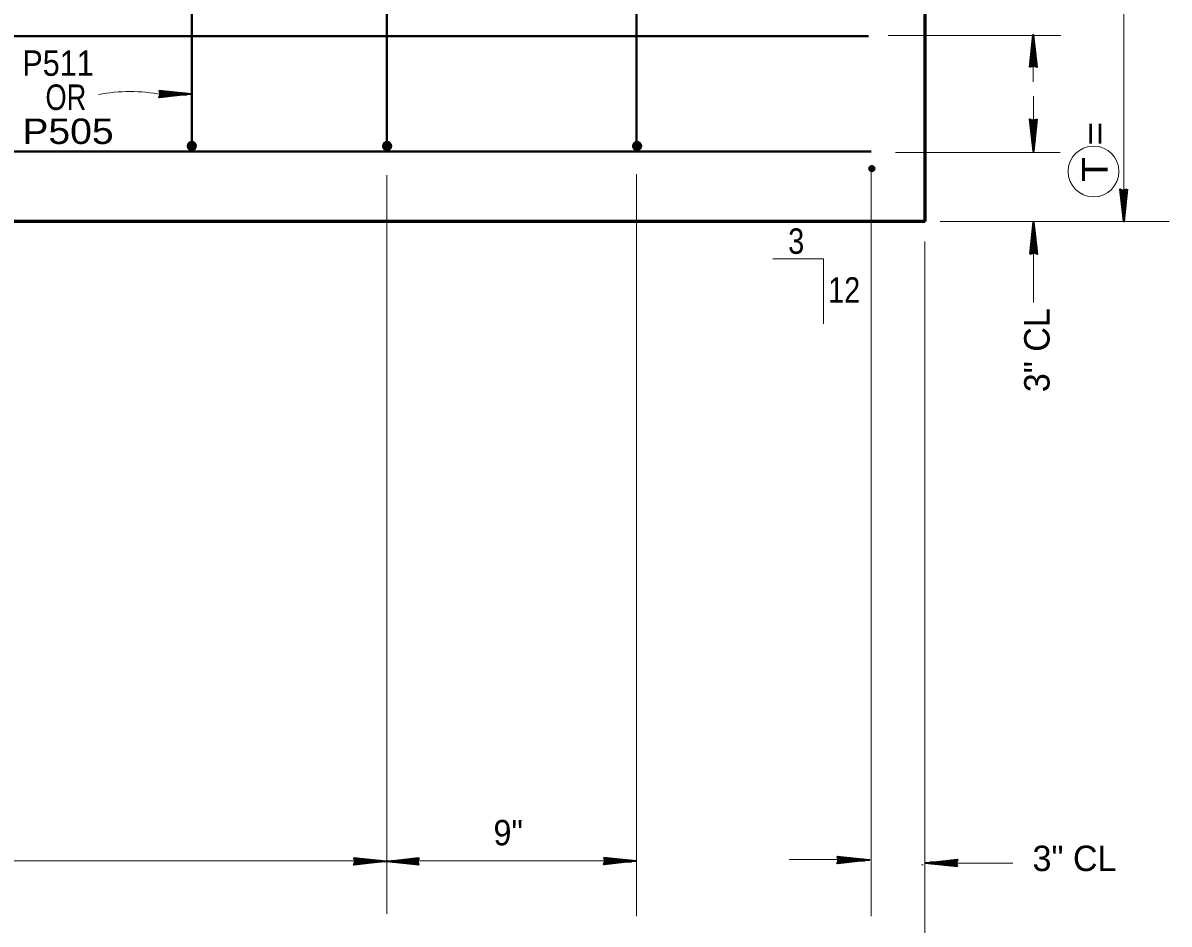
# Model space of a CAD drawing. Extents: x 6.34 to 9.53, y -1.46 to 0.53.
# Drawn here: x 7.0899 to 7.4656, y -1.0365 to -0.7412 of the extents above; entities that cross this region are included whole.
import ezdxf
from ezdxf.enums import TextEntityAlignment as Align

# ---------------------------------------------------------------- set-up
doc = ezdxf.new("R2010")
doc.units = 0
doc.header["$LTSCALE"] = 0.0033
doc.header["$PDMODE"] = 32
doc.header["$PDSIZE"] = 0.00165
doc.layers.add('1', color=7, linetype='Continuous', lineweight=40)

msp = doc.modelspace()

# ---------------------------------------------------------------- linework, layer by layer
at = {"layer": '1', "lineweight": 13}
for p, q in [((7.45075, -0.391417), (7.45075, -0.80625)), ((7.3735, -0.74525), (7.430083, -0.74525)), ((7.421083, -0.7605), (7.421083, -0.750583)), ((7.421167, -0.775), (7.421167, -0.765167)), ((7.209167, -0.774333), (7.209167, -0.782)), ((7.375917, -0.783583), (7.429917, -0.783583)), ((7.367917, -0.78775), (7.367917, -1.033917)), ((7.209167, -0.791083), (7.209167, -1.033083)), ((7.291083, -0.79075), (7.291083, -1.033917)), ((7.367917, -0.795917), (7.367917, -0.7975)), ((7.385583, -0.80625), (7.385583, -0.806583)), ((7.390583, -0.80625), (7.465583, -0.80625)), ((7.385583, -0.81275), (7.385583, -0.8945)), ((7.335667, -0.818417), (7.352333, -0.818417)), ((7.352333, -0.818417), (7.352333, -0.83975)), ((7.421167, -0.83275), (7.421167, -0.81625)), ((7.385583, -0.892917), (7.385583, -1.077833)), ((7.290917, -1.01575), (6.739167, -1.01575)), ((7.341083, -1.01525), (7.361917, -1.01525)), ((7.384417, -1.017), (7.385, -1.017)), ((7.393583, -1.0165), (7.414417, -1.0165)), ((7.291083, -1.0215), (7.291083, -1.02725)), ((7.209167, -1.024167), (7.209167, -1.029417))]:
    msp.add_line(p, q, dxfattribs=at)
at = {"layer": '1'}
for p, q in [((7.14525, -0.667917), (7.14525, -0.780417)), ((7.209167, -0.667917), (7.209167, -0.780333)), ((7.291083, -0.667667), (7.291083, -0.78)), ((7.144667, -0.780333), (7.144333, -0.782333)), ((7.14475, -0.780417), (7.144417, -0.782333)), ((7.144833, -0.780417), (7.1445, -0.782333)), ((7.144917, -0.780417), (7.144583, -0.782417)), ((7.146083, -0.780583), (7.144583, -0.7805)), ((7.146083, -0.780667), (7.144583, -0.780583)), ((7.146083, -0.78075), (7.144583, -0.780667)), ((7.146083, -0.780833), (7.144583, -0.78075)), ((7.146083, -0.780917), (7.144583, -0.780833)), ((7.146083, -0.781083), (7.144583, -0.781)), ((7.146083, -0.781167), (7.144583, -0.781083)), ((7.146083, -0.78125), (7.144583, -0.781167)), ((7.146083, -0.781333), (7.144583, -0.78125)), ((7.145167, -0.780417), (7.14475, -0.782417)), ((7.145333, -0.7805), (7.144917, -0.782417)), ((7.145417, -0.7805), (7.145, -0.782417)), ((7.1455, -0.7805), (7.145083, -0.7825)), ((7.145583, -0.7805), (7.14525, -0.7825)), ((7.145667, -0.780583), (7.145333, -0.7825)), ((7.145833, -0.780583), (7.145417, -0.782583)), ((7.145917, -0.780583), (7.1455, -0.782583)), ((7.146, -0.780583), (7.145667, -0.782583)), ((7.146083, -0.780583), (7.14575, -0.782583)), ((7.14625, -0.780667), (7.145917, -0.782583)), ((7.208667, -0.780333), (7.208333, -0.782333)), ((7.20875, -0.780417), (7.208417, -0.782333)), ((7.208833, -0.780417), (7.2085, -0.782333)), ((7.208917, -0.780417), (7.208583, -0.782417)), ((7.210083, -0.780583), (7.208583, -0.7805)), ((7.210083, -0.780667), (7.208583, -0.780583)), ((7.210083, -0.78075), (7.208583, -0.780667)), ((7.210083, -0.780833), (7.208583, -0.78075)), ((7.210083, -0.780917), (7.208583, -0.780833)), ((7.210083, -0.781083), (7.208583, -0.781)), ((7.210083, -0.781167), (7.208583, -0.781083)), ((7.210083, -0.78125), (7.208583, -0.781167)), ((7.210083, -0.781333), (7.208583, -0.78125)), ((7.209167, -0.780417), (7.20875, -0.782417)), ((7.209333, -0.7805), (7.208917, -0.782417)), ((7.209417, -0.7805), (7.209, -0.782417)), ((7.2095, -0.7805), (7.209083, -0.7825)), ((7.209583, -0.7805), (7.20925, -0.7825)), ((7.209667, -0.780583), (7.209333, -0.7825)), ((7.209833, -0.780583), (7.209417, -0.782583)), ((7.209917, -0.780583), (7.2095, -0.782583)), ((7.21, -0.780583), (7.209667, -0.782583)), ((7.210083, -0.780583), (7.20975, -0.782583)), ((7.21025, -0.780667), (7.209917, -0.782583)), ((7.290583, -0.780333), (7.29025, -0.782333)), ((7.290667, -0.780417), (7.290333, -0.782333)), ((7.29075, -0.780417), (7.290417, -0.782333)), ((7.290833, -0.780417), (7.2905, -0.782417)), ((7.292, -0.780583), (7.2905, -0.7805)), ((7.292, -0.780667), (7.2905, -0.780583)), ((7.292, -0.78075), (7.2905, -0.780667)), ((7.292, -0.780833), (7.2905, -0.78075)), ((7.292, -0.780917), (7.2905, -0.780833)), ((7.292, -0.781083), (7.2905, -0.781)), ((7.292, -0.781167), (7.2905, -0.781083)), ((7.292, -0.78125), (7.2905, -0.781167)), ((7.292, -0.781333), (7.2905, -0.78125)), ((7.291083, -0.780417), (7.290667, -0.782417)), ((7.29125, -0.7805), (7.290833, -0.782417)), ((7.291333, -0.7805), (7.290917, -0.782417)), ((7.291417, -0.7805), (7.291, -0.7825)), ((7.2915, -0.7805), (7.291167, -0.7825)), ((7.291583, -0.780583), (7.29125, -0.7825)), ((7.29175, -0.780583), (7.291333, -0.782583)), ((7.291833, -0.780583), (7.291417, -0.782583)), ((7.291917, -0.780583), (7.291583, -0.782583)), ((7.292, -0.780583), (7.291667, -0.782583)), ((7.292167, -0.780667), (7.291833, -0.782583)), ((7.146, -0.78175), (7.1445, -0.781583)), ((7.146, -0.781917), (7.1445, -0.78175)), ((7.146, -0.782), (7.1445, -0.781917)), ((7.146, -0.782), (7.1445, -0.781917)), ((7.146, -0.782083), (7.1445, -0.782)), ((7.146, -0.782167), (7.1445, -0.782083)), ((7.146, -0.78225), (7.1445, -0.782167)), ((7.146, -0.782333), (7.1445, -0.78225)), ((7.146, -0.782417), (7.1445, -0.782333)), ((7.146, -0.7825), (7.1445, -0.782417)), ((7.146, -0.782667), (7.1445, -0.782583)), ((7.146083, -0.781417), (7.144583, -0.781333)), ((7.146083, -0.7815), (7.144583, -0.781417)), ((7.146083, -0.781583), (7.144583, -0.7815)), ((7.21, -0.78175), (7.2085, -0.781583)), ((7.21, -0.781917), (7.2085, -0.78175)), ((7.21, -0.782), (7.2085, -0.781917)), ((7.21, -0.782), (7.2085, -0.781917)), ((7.21, -0.782083), (7.2085, -0.782)), ((7.21, -0.782167), (7.2085, -0.782083)), ((7.21, -0.78225), (7.2085, -0.782167)), ((7.21, -0.782333), (7.2085, -0.78225)), ((7.21, -0.782417), (7.2085, -0.782333)), ((7.21, -0.7825), (7.2085, -0.782417)), ((7.21, -0.782667), (7.2085, -0.782583)), ((7.210083, -0.781417), (7.208583, -0.781333)), ((7.210083, -0.7815), (7.208583, -0.781417)), ((7.210083, -0.781583), (7.208583, -0.7815)), ((7.291917, -0.78175), (7.290417, -0.781583)), ((7.291917, -0.781917), (7.290417, -0.78175)), ((7.291917, -0.782), (7.290417, -0.781917)), ((7.291917, -0.782), (7.290417, -0.781917)), ((7.291917, -0.782083), (7.290417, -0.782)), ((7.291917, -0.782167), (7.290417, -0.782083)), ((7.291917, -0.78225), (7.290417, -0.782167)), ((7.291917, -0.782333), (7.290417, -0.78225)), ((7.291917, -0.782417), (7.290417, -0.782333)), ((7.291917, -0.7825), (7.290417, -0.782417)), ((7.291917, -0.782667), (7.290417, -0.782583)), ((7.292, -0.781417), (7.2905, -0.781333)), ((7.292, -0.7815), (7.2905, -0.781417)), ((7.292, -0.781583), (7.2905, -0.7815))]:
    msp.add_line(p, q, dxfattribs=at)
at = {"layer": '1', "lineweight": 35}
for p, q in [((7.421083, -0.755667), (7.421083, -0.745083)), ((7.420083, -0.755417), (7.421, -0.747583)), ((7.420083, -0.755417), (7.421, -0.747583)), ((7.420167, -0.755417), (7.421, -0.747583)), ((7.42025, -0.755417), (7.421083, -0.747583)), ((7.42025, -0.755417), (7.42125, -0.747583)), ((7.42175, -0.7555), (7.421, -0.748167)), ((7.421917, -0.755417), (7.421083, -0.748083)), ((7.422, -0.755417), (7.42125, -0.748083)), ((7.422167, -0.755417), (7.421333, -0.748083)), ((7.134583, -0.764417), (7.145167, -0.764417)), ((7.13475, -0.765083), (7.142083, -0.764333)), ((7.134833, -0.763417), (7.142667, -0.764333)), ((7.134833, -0.763417), (7.142667, -0.764333)), ((7.134833, -0.7635), (7.142667, -0.764333)), ((7.134833, -0.763583), (7.142667, -0.764417)), ((7.134833, -0.763583), (7.142667, -0.764583)), ((7.134833, -0.76525), (7.142167, -0.764417)), ((7.134833, -0.765333), (7.142167, -0.764583)), ((7.134833, -0.7655), (7.142167, -0.764667)), ((7.420083, -0.772917), (7.420917, -0.78025)), ((7.42025, -0.772917), (7.421, -0.78025)), ((7.420333, -0.772917), (7.421167, -0.78025)), ((7.4205, -0.772833), (7.42125, -0.780167)), ((7.422, -0.772917), (7.421, -0.78075)), ((7.421167, -0.772667), (7.421167, -0.78325)), ((7.422, -0.772917), (7.421167, -0.78075)), ((7.422167, -0.772917), (7.42125, -0.78075)), ((7.422167, -0.772917), (7.42125, -0.78075)), ((7.422083, -0.772917), (7.42125, -0.78075)), ((7.449667, -0.795917), (7.4505, -0.80325)), ((7.449833, -0.795917), (7.450583, -0.80325)), ((7.449917, -0.795917), (7.45075, -0.80325)), ((7.450083, -0.795833), (7.450833, -0.803167)), ((7.451583, -0.795917), (7.450583, -0.80375)), ((7.45075, -0.795667), (7.45075, -0.80625)), ((7.451583, -0.795917), (7.45075, -0.80375)), ((7.45175, -0.795917), (7.450833, -0.80375)), ((7.45175, -0.795917), (7.450833, -0.80375)), ((7.451667, -0.795917), (7.450833, -0.80375)), ((7.421167, -0.816917), (7.421167, -0.806333)), ((7.420167, -0.816667), (7.421083, -0.808833)), ((7.420167, -0.816667), (7.421083, -0.808833)), ((7.42025, -0.816667), (7.421083, -0.808833)), ((7.420333, -0.816667), (7.421167, -0.808833)), ((7.420333, -0.816667), (7.421333, -0.808833)), ((7.421833, -0.81675), (7.421083, -0.809417)), ((7.422, -0.816667), (7.421167, -0.809333)), ((7.422083, -0.816667), (7.421333, -0.809333)), ((7.42225, -0.816667), (7.421417, -0.809333)), ((7.198417, -1.015833), (7.209, -1.015833)), ((7.198583, -1.0165), (7.205917, -1.01575)), ((7.198667, -1.014833), (7.2065, -1.01575)), ((7.198667, -1.014833), (7.2065, -1.01575)), ((7.198667, -1.014917), (7.2065, -1.01575)), ((7.198667, -1.015), (7.2065, -1.015833)), ((7.198667, -1.015), (7.2065, -1.016)), ((7.198667, -1.016667), (7.206, -1.015833)), ((7.198667, -1.01675), (7.206, -1.016)), ((7.198667, -1.016917), (7.206, -1.016083)), ((7.21975, -1.016), (7.209167, -1.016)), ((7.2195, -1.016833), (7.211667, -1.015833)), ((7.2195, -1.016833), (7.211667, -1.016)), ((7.2195, -1.017), (7.211667, -1.016083)), ((7.2195, -1.017), (7.211667, -1.016083)), ((7.2195, -1.016917), (7.211667, -1.016083)), ((7.2195, -1.014917), (7.212167, -1.01575)), ((7.2195, -1.015083), (7.212167, -1.015833)), ((7.2195, -1.015167), (7.212167, -1.016)), ((7.219583, -1.015333), (7.21225, -1.016083)), ((7.280333, -1.01575), (7.290917, -1.01575)), ((7.2805, -1.016417), (7.287833, -1.015667)), ((7.280583, -1.01475), (7.288417, -1.015667)), ((7.280583, -1.01475), (7.288417, -1.015667)), ((7.280583, -1.014833), (7.288417, -1.015667)), ((7.280583, -1.014917), (7.288417, -1.01575)), ((7.280583, -1.014917), (7.288417, -1.015917)), ((7.280583, -1.016583), (7.287917, -1.01575)), ((7.280583, -1.016667), (7.287917, -1.015917)), ((7.280583, -1.016833), (7.287917, -1.016)), ((7.356833, -1.015417), (7.367417, -1.015417)), ((7.357, -1.016083), (7.364333, -1.015333)), ((7.357083, -1.014417), (7.364917, -1.015333)), ((7.357083, -1.014417), (7.364917, -1.015333)), ((7.357083, -1.0145), (7.364917, -1.015333)), ((7.357083, -1.014583), (7.364917, -1.015417)), ((7.357083, -1.014583), (7.364917, -1.015583)), ((7.357083, -1.01625), (7.364417, -1.015417)), ((7.357083, -1.016333), (7.364417, -1.015583)), ((7.357083, -1.0165), (7.364417, -1.015667)), ((7.39625, -1.0165), (7.385667, -1.0165)), ((7.396, -1.017333), (7.388167, -1.016333)), ((7.396, -1.017333), (7.388167, -1.0165)), ((7.396, -1.0175), (7.388167, -1.016583)), ((7.396, -1.0175), (7.388167, -1.016583)), ((7.396, -1.017417), (7.388167, -1.016583)), ((7.396, -1.015417), (7.388667, -1.01625)), ((7.396, -1.015583), (7.388667, -1.016333)), ((7.396, -1.015667), (7.388667, -1.0165)), ((7.396083, -1.015833), (7.38875, -1.016583))]:
    msp.add_line(p, q, dxfattribs=at)
at = {"layer": '1', "lineweight": 60}
msp.add_line((7.385583, -0.80625), (6.635583, -0.80625), dxfattribs=at)
msp.add_lwpolyline([(7.30225, -0.389583), (7.30225, -0.722917), (7.385583, -0.722917), (7.385583, -0.80625)], dxfattribs=at)
at = {"layer": '1'}
for points in [[(6.962083, -0.741333), (7.024417, -0.741333), (7.031667, -0.7455), (7.367083, -0.7455)], [(6.962167, -0.779083), (7.02375, -0.779083), (7.031, -0.78325), (7.367917, -0.78325)], [(7.14525, -0.780167), (7.145583, -0.78275), (7.146083, -0.780417), (7.145, -0.78275), (7.144583, -0.780333), (7.14425, -0.782333), (7.146333, -0.782333), (7.144, -0.781417), (7.146583, -0.781667), (7.14425, -0.780667), (7.146583, -0.781), (7.144, -0.781833), (7.14575, -0.78025), (7.145917, -0.782667), (7.144083, -0.781), (7.1465, -0.782083), (7.146083, -0.780417), (7.144583, -0.780333), (7.144, -0.781417), (7.14425, -0.782333), (7.145, -0.78275), (7.145917, -0.782667), (7.1465, -0.782083), (7.145417, -0.781417), (7.1445, -0.782583), (7.14425, -0.780667), (7.145417, -0.781417), (7.145917, -0.780333), (7.146583, -0.781333), (7.1455, -0.781417), (7.14425, -0.78225), (7.1455, -0.78025), (7.145833, -0.781583), (7.146333, -0.782333)], [(7.20925, -0.780167), (7.209583, -0.78275), (7.210083, -0.780417), (7.209, -0.78275), (7.208583, -0.780333), (7.20825, -0.782333), (7.210333, -0.782333), (7.208, -0.781417), (7.210583, -0.781667), (7.20825, -0.780667), (7.210583, -0.781), (7.208, -0.781833), (7.20975, -0.78025), (7.209917, -0.782667), (7.208083, -0.781), (7.2105, -0.782083), (7.210083, -0.780417), (7.208583, -0.780333), (7.208, -0.781417), (7.20825, -0.782333), (7.209, -0.78275), (7.209917, -0.782667), (7.2105, -0.782083), (7.209417, -0.781417), (7.2085, -0.782583), (7.20825, -0.780667), (7.209417, -0.781417), (7.209917, -0.780333), (7.210583, -0.781333), (7.2095, -0.781417), (7.20825, -0.78225), (7.2095, -0.78025), (7.209833, -0.781583), (7.210333, -0.782333)], [(7.291167, -0.780167), (7.2915, -0.78275), (7.292, -0.780417), (7.290917, -0.78275), (7.2905, -0.780333), (7.290167, -0.782333), (7.29225, -0.782333), (7.289917, -0.781417), (7.2925, -0.781667), (7.290167, -0.780667), (7.2925, -0.781), (7.289917, -0.781833), (7.291667, -0.78025), (7.291833, -0.782667), (7.29, -0.781), (7.292417, -0.782083), (7.292, -0.780417), (7.2905, -0.780333), (7.289917, -0.781417), (7.290167, -0.782333), (7.290917, -0.78275), (7.291833, -0.782667), (7.292417, -0.782083), (7.291333, -0.781417), (7.290417, -0.782583), (7.290167, -0.780667), (7.291333, -0.781417), (7.291833, -0.780333), (7.2925, -0.781333), (7.291417, -0.781417), (7.290167, -0.78225), (7.291417, -0.78025), (7.29175, -0.781583), (7.29225, -0.782333)]]:
    msp.add_lwpolyline(points, dxfattribs=at)
at = {"layer": '1', "lineweight": 35}
for points in [[(7.42, -0.755667), (7.421083, -0.745083), (7.42225, -0.755667), (7.421083, -0.755083)], [(7.421, -0.754917), (7.420917, -0.75025), (7.421, -0.75025), (7.421, -0.751167), (7.420917, -0.754917), (7.420833, -0.751917), (7.42075, -0.755083), (7.420667, -0.752833), (7.420583, -0.755083), (7.420833, -0.751583), (7.421, -0.746917), (7.42125, -0.747833), (7.42125, -0.746583), (7.42125, -0.754917), (7.421417, -0.7525), (7.421417, -0.755083), (7.421, -0.74975), (7.421667, -0.755083)], [(7.134583, -0.763333), (7.145167, -0.764417), (7.134583, -0.765583), (7.135167, -0.764417)], [(7.135333, -0.764333), (7.14, -0.76425), (7.14, -0.764333), (7.139083, -0.764333), (7.135333, -0.76425), (7.138333, -0.764167), (7.135167, -0.764083), (7.137417, -0.764), (7.135167, -0.763917), (7.138667, -0.764167), (7.143333, -0.764333), (7.142417, -0.764583), (7.143667, -0.764583), (7.135333, -0.764583), (7.13775, -0.76475), (7.135167, -0.76475), (7.1405, -0.764333), (7.135167, -0.765)], [(7.42225, -0.772667), (7.421167, -0.78325), (7.42, -0.772667), (7.421167, -0.77325)], [(7.42125, -0.773417), (7.421333, -0.778083), (7.42125, -0.778083), (7.42125, -0.777167), (7.421333, -0.773417), (7.421417, -0.776417), (7.4215, -0.77325), (7.421583, -0.7755), (7.421667, -0.77325), (7.421417, -0.77675), (7.42125, -0.781417), (7.421, -0.7805), (7.421, -0.78175), (7.421, -0.773417), (7.420833, -0.775833), (7.420833, -0.77325), (7.42125, -0.778583), (7.420583, -0.77325)], [(7.451833, -0.795667), (7.45075, -0.80625), (7.449583, -0.795667), (7.45075, -0.79625)], [(7.450833, -0.796417), (7.450917, -0.801083), (7.450833, -0.801083), (7.450833, -0.800167), (7.450917, -0.796417), (7.451, -0.799417), (7.451083, -0.79625), (7.451167, -0.7985), (7.45125, -0.79625), (7.451, -0.79975), (7.450833, -0.804417), (7.450583, -0.8035), (7.450583, -0.80475), (7.450583, -0.796417), (7.450417, -0.798833), (7.450417, -0.79625), (7.450833, -0.801583), (7.450167, -0.79625)], [(7.420083, -0.816917), (7.421167, -0.806333), (7.422333, -0.816917), (7.421167, -0.816333)], [(7.421083, -0.816167), (7.421, -0.8115), (7.421083, -0.8115), (7.421083, -0.812417), (7.421, -0.816167), (7.420917, -0.813167), (7.420833, -0.816333), (7.42075, -0.814083), (7.420667, -0.816333), (7.420917, -0.812833), (7.421083, -0.808167), (7.421333, -0.809083), (7.421333, -0.807833), (7.421333, -0.816167), (7.4215, -0.81375), (7.4215, -0.816333), (7.421083, -0.811), (7.42175, -0.816333)], [(7.198417, -1.01475), (7.209, -1.015833), (7.198417, -1.017), (7.199, -1.015833)], [(7.199167, -1.01575), (7.203833, -1.015667), (7.203833, -1.01575), (7.202917, -1.01575), (7.199167, -1.015667), (7.202167, -1.015583), (7.199, -1.0155), (7.20125, -1.015417), (7.199, -1.015333), (7.2025, -1.015583), (7.207167, -1.01575), (7.20625, -1.016), (7.2075, -1.016), (7.199167, -1.016), (7.201583, -1.016167), (7.199, -1.016167), (7.204333, -1.01575), (7.199, -1.016417)], [(7.21975, -1.017083), (7.209167, -1.016), (7.21975, -1.014833), (7.219167, -1.016)], [(7.219, -1.016083), (7.214333, -1.016167), (7.214333, -1.016083), (7.21525, -1.016083), (7.219, -1.016167), (7.216, -1.01625), (7.219167, -1.016333), (7.216917, -1.016417), (7.219167, -1.0165), (7.215667, -1.01625), (7.211, -1.016083), (7.211917, -1.015833), (7.210667, -1.015833), (7.219, -1.015833), (7.216583, -1.015667), (7.219167, -1.015667), (7.213833, -1.016083), (7.219167, -1.015417)], [(7.280333, -1.014667), (7.290917, -1.01575), (7.280333, -1.016917), (7.280917, -1.01575)], [(7.281083, -1.015667), (7.28575, -1.015583), (7.28575, -1.015667), (7.284833, -1.015667), (7.281083, -1.015583), (7.284083, -1.0155), (7.280917, -1.015417), (7.283167, -1.015333), (7.280917, -1.01525), (7.284417, -1.0155), (7.289083, -1.015667), (7.288167, -1.015917), (7.289417, -1.015917), (7.281083, -1.015917), (7.2835, -1.016083), (7.280917, -1.016083), (7.28625, -1.015667), (7.280917, -1.016333)], [(7.356833, -1.014333), (7.367417, -1.015417), (7.356833, -1.016583), (7.357417, -1.015417)], [(7.357583, -1.015333), (7.36225, -1.01525), (7.36225, -1.015333), (7.361333, -1.015333), (7.357583, -1.01525), (7.360583, -1.015167), (7.357417, -1.015083), (7.359667, -1.015), (7.357417, -1.014917), (7.360917, -1.015167), (7.365583, -1.015333), (7.364667, -1.015583), (7.365917, -1.015583), (7.357583, -1.015583), (7.36, -1.01575), (7.357417, -1.01575), (7.36275, -1.015333), (7.357417, -1.016)], [(7.39625, -1.017583), (7.385667, -1.0165), (7.39625, -1.015333), (7.395667, -1.0165)], [(7.3955, -1.016583), (7.390833, -1.016667), (7.390833, -1.016583), (7.39175, -1.016583), (7.3955, -1.016667), (7.3925, -1.01675), (7.395667, -1.016833), (7.393417, -1.016917), (7.395667, -1.017), (7.392167, -1.01675), (7.3875, -1.016583), (7.388417, -1.016333), (7.387167, -1.016333), (7.3955, -1.016333), (7.393083, -1.016167), (7.395667, -1.016167), (7.390333, -1.016583), (7.395667, -1.015917)]]:
    msp.add_lwpolyline(points, close=True, dxfattribs=at)
for points in [[(7.421, -0.754917), (7.42025, -0.755333), (7.4205, -0.755083), (7.420833, -0.754917), (7.42075, -0.754667), (7.420417, -0.754833), (7.421167, -0.755), (7.421667, -0.755167), (7.422083, -0.755417)], [(7.135333, -0.764333), (7.134917, -0.763583), (7.135167, -0.763833), (7.135333, -0.764167), (7.135583, -0.764083), (7.135417, -0.76375), (7.13525, -0.7645), (7.135083, -0.765), (7.134833, -0.765417)], [(7.42125, -0.773417), (7.422, -0.773), (7.42175, -0.77325), (7.421417, -0.773417), (7.4215, -0.773667), (7.421833, -0.7735), (7.421083, -0.773333), (7.420583, -0.773167), (7.420167, -0.772917)], [(7.450833, -0.796417), (7.451583, -0.796), (7.451333, -0.79625), (7.451, -0.796417), (7.451083, -0.796667), (7.451417, -0.7965), (7.450667, -0.796333), (7.450167, -0.796167), (7.44975, -0.795917)], [(7.421083, -0.816167), (7.420333, -0.816583), (7.420583, -0.816333), (7.420917, -0.816167), (7.420833, -0.815917), (7.4205, -0.816083), (7.42125, -0.81625), (7.42175, -0.816417), (7.422167, -0.816667)], [(7.199167, -1.01575), (7.19875, -1.015), (7.199, -1.01525), (7.199167, -1.015583), (7.199417, -1.0155), (7.19925, -1.015167), (7.199083, -1.015917), (7.198917, -1.016417), (7.198667, -1.016833)], [(7.219, -1.016083), (7.219417, -1.016833), (7.219167, -1.016583), (7.219, -1.01625), (7.21875, -1.016333), (7.218917, -1.016667), (7.219083, -1.015917), (7.21925, -1.015417), (7.2195, -1.015)], [(7.281083, -1.015667), (7.280667, -1.014917), (7.280917, -1.015167), (7.281083, -1.0155), (7.281333, -1.015417), (7.281167, -1.015083), (7.281, -1.015833), (7.280833, -1.016333), (7.280583, -1.01675)], [(7.357583, -1.015333), (7.357167, -1.014583), (7.357417, -1.014833), (7.357583, -1.015167), (7.357833, -1.015083), (7.357667, -1.01475), (7.3575, -1.0155), (7.357333, -1.016), (7.357083, -1.016417)], [(7.3955, -1.016583), (7.395917, -1.017333), (7.395667, -1.017083), (7.3955, -1.01675), (7.39525, -1.016833), (7.395417, -1.017167), (7.395583, -1.016417), (7.39575, -1.015917), (7.396, -1.0155)]]:
    msp.add_lwpolyline(points, dxfattribs=at)
at = {"layer": '1'}
for centre in [(7.1453, -0.7815), (7.2093, -0.7815), (7.291217, -0.7815)]:
    msp.add_circle(centre, 0.00132, dxfattribs=at)
at = {"layer": '1', "lineweight": 13}
msp.add_circle((7.440833, -0.789833), 0.008333, dxfattribs=at)
msp.add_arc((7.125042, -0.816655), 0.052998, 78.8025, 101.1975, dxfattribs=at)
at = {"layer": '1'}
msp.add_point((7.368167, -0.788917), dxfattribs=at)

# ---------------------------------------------------------------- texts
for s, width, p in [('P511', 0.9, (7.08975, -0.7585)), ('OR', 0.8, (7.097333, -0.769667)), ('P505', 1.15, (7.08975, -0.780833)), ('12', 0.85, (7.353833, -0.832833)), ('9"', 0.95, (7.244167, -1.010667))]:
    msp.add_text(s, height=0.008334, dxfattribs=dict(at, width=width)).set_placement(p)
at = {"layer": '1', "width": 1.2}
msp.add_text('T =      ', height=0.008334, rotation=90, dxfattribs=at).set_placement((7.445417, -0.79325))
at = {"layer": '1', "width": 0.85}
msp.add_text('3', height=0.008334, dxfattribs=at).set_placement((7.343375, -0.816833), align=Align.CENTER)
at = {"layer": '1'}
msp.add_text('3" CL', height=0.008334, rotation=90, dxfattribs=at).set_placement((7.426417, -0.862167))
msp.add_text('3" CL', height=0.008334, dxfattribs=at).set_placement((7.420833, -1.019083))

doc.saveas('drawing.dxf')
